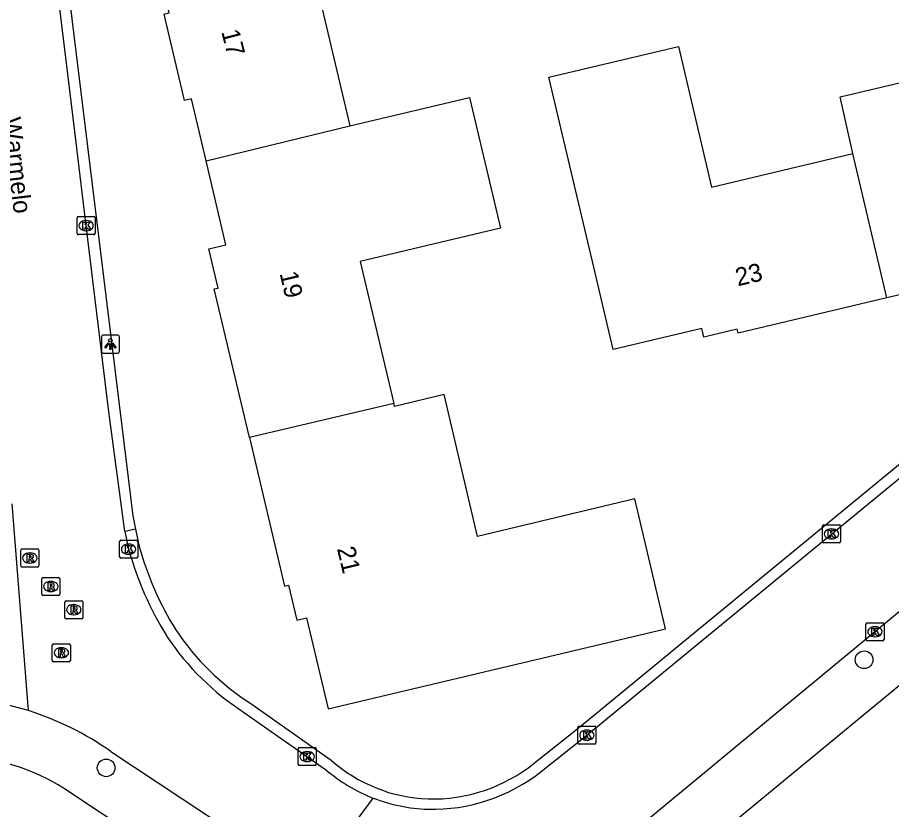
# Model space of a CAD drawing. Extents: x 157663 to 158496, y 379212 to 380934.
# Drawn here: x 158156.17 to 158204.55, y 380451.91 to 380495.74 of the extents above; entities that cross this region are included whole.
import ezdxf

# ---------------------------------------------------------------- set-up
doc = ezdxf.new("R2010")
doc.units = 0
for name, color, linetype in [('IMGEO_Boom', 7, 'Continuous'), ('IMGEO_Kolk', 7, 'Continuous'), ('IMGEO_Lichtpunt', 7, 'Continuous'), ('IMGEO_Openbare_ruimte_label', 7, 'Continuous'), ('IMGEO_Pand', 7, 'Continuous'), ('IMGEO_Pand_nummerreeks', 7, 'Continuous'), ('IMGEO_Rijbaan_lokaal_open', 7, 'Continuous'), ('IMGEO_Rioolput', 7, 'Continuous'), ('IMGEO_Voetpad_open', 7, 'Continuous')]:
    doc.layers.add(name, color=color, linetype=linetype)

msp = doc.modelspace()

# ---------------------------------------------------------------- linework, layer by layer
at = {"layer": 'IMGEO_Boom'}
for centre in [(158203.034, 380460.198), (158161.074, 380454.213)]:
    msp.add_circle(centre, 0.489, dxfattribs=at)
at = {"layer": 'IMGEO_Kolk'}
for p, q in [((158159.462, 380483.793), (158159.462, 380484.645)), ((158159.537, 380484.719), (158160.389, 380484.719)), ((158159.95, 380484.499), (158159.975, 380484.499)), ((158160.463, 380484.645), (158160.463, 380483.793)), ((158159.973, 380483.939), (158159.948, 380483.939)), ((158160.389, 380483.719), (158159.537, 380483.719)), ((158200.727, 380466.732), (158200.727, 380467.584)), ((158200.802, 380467.658), (158201.654, 380467.658)), ((158201.215, 380467.438), (158201.24, 380467.438)), ((158201.728, 380467.584), (158201.728, 380466.732)), ((158161.818, 380465.888), (158161.818, 380466.74)), ((158161.893, 380466.814), (158162.745, 380466.814)), ((158162.306, 380466.594), (158162.331, 380466.594)), ((158162.819, 380466.74), (158162.819, 380465.888)), ((158201.654, 380466.658), (158200.802, 380466.658)), ((158201.238, 380466.878), (158201.213, 380466.878)), ((158162.329, 380466.034), (158162.304, 380466.034)), ((158162.745, 380465.814), (158161.893, 380465.814)), ((158203.135, 380461.319), (158203.135, 380462.171)), ((158203.21, 380462.245), (158204.062, 380462.245)), ((158204.136, 380462.171), (158204.136, 380461.319)), ((158203.623, 380462.025), (158203.648, 380462.025)), ((158204.062, 380461.245), (158203.21, 380461.245)), ((158203.646, 380461.465), (158203.621, 380461.465)), ((158187.188, 380455.594), (158187.188, 380456.446)), ((158187.263, 380456.52), (158188.115, 380456.52)), ((158187.676, 380456.3), (158187.701, 380456.3)), ((158188.189, 380456.446), (158188.189, 380455.594)), ((158171.775, 380455.337), (158172.627, 380455.337)), ((158188.115, 380455.52), (158187.263, 380455.52)), ((158187.699, 380455.74), (158187.674, 380455.74)), ((158171.7, 380454.411), (158171.7, 380455.263)), ((158172.188, 380455.117), (158172.213, 380455.117)), ((158172.701, 380455.263), (158172.701, 380454.411)), ((158172.627, 380454.337), (158171.775, 380454.337)), ((158172.211, 380454.557), (158172.186, 380454.557))]:
    msp.add_line(p, q, dxfattribs=at)
for points in [[(158159.462, 380483.793), (158159.462, 380484.645)], [(158159.537, 380484.719), (158160.389, 380484.719)], [(158159.783, 380484.419), (158159.906, 380484.419), (158159.906, 380484.268), (158160.036, 380484.419), (158160.2, 380484.419), (158160.054, 380484.268), (158160.207, 380484.019), (158160.055, 380484.019), (158159.97, 380484.183), (158159.906, 380484.116), (158159.906, 380484.019), (158159.783, 380484.019), (158159.783, 380484.419)], [(158160.463, 380484.645), (158160.463, 380483.793)], [(158160.389, 380483.719), (158159.537, 380483.719)], [(158200.727, 380466.732), (158200.727, 380467.584)], [(158200.802, 380467.658), (158201.654, 380467.658)], [(158201.728, 380467.584), (158201.728, 380466.732)], [(158201.048, 380467.358), (158201.171, 380467.358), (158201.171, 380467.207), (158201.301, 380467.358), (158201.465, 380467.358), (158201.319, 380467.207), (158201.472, 380466.958), (158201.32, 380466.958), (158201.235, 380467.122), (158201.171, 380467.055), (158201.171, 380466.958), (158201.048, 380466.958), (158201.048, 380467.358)], [(158161.818, 380465.888), (158161.818, 380466.74)], [(158161.893, 380466.814), (158162.745, 380466.814)], [(158162.139, 380466.514), (158162.262, 380466.514), (158162.262, 380466.363), (158162.392, 380466.514), (158162.556, 380466.514), (158162.41, 380466.363), (158162.563, 380466.114), (158162.411, 380466.114), (158162.326, 380466.278), (158162.262, 380466.211), (158162.262, 380466.114), (158162.139, 380466.114), (158162.139, 380466.514)], [(158162.819, 380466.74), (158162.819, 380465.888)], [(158201.654, 380466.658), (158200.802, 380466.658)], [(158162.745, 380465.814), (158161.893, 380465.814)], [(158203.135, 380461.319), (158203.135, 380462.171)], [(158203.21, 380462.245), (158204.062, 380462.245)], [(158204.136, 380462.171), (158204.136, 380461.319)], [(158203.456, 380461.945), (158203.579, 380461.945), (158203.579, 380461.794), (158203.709, 380461.945), (158203.873, 380461.945), (158203.727, 380461.794), (158203.88, 380461.545), (158203.728, 380461.545), (158203.643, 380461.709), (158203.579, 380461.642), (158203.579, 380461.545), (158203.456, 380461.545), (158203.456, 380461.945)], [(158204.062, 380461.245), (158203.21, 380461.245)], [(158187.188, 380455.594), (158187.188, 380456.446)], [(158187.263, 380456.52), (158188.115, 380456.52)], [(158188.189, 380456.446), (158188.189, 380455.594)], [(158187.509, 380456.22), (158187.632, 380456.22), (158187.632, 380456.069), (158187.762, 380456.22), (158187.926, 380456.22), (158187.78, 380456.069), (158187.933, 380455.82), (158187.781, 380455.82), (158187.696, 380455.984), (158187.632, 380455.917), (158187.632, 380455.82), (158187.509, 380455.82), (158187.509, 380456.22)], [(158171.775, 380455.337), (158172.627, 380455.337)], [(158188.115, 380455.52), (158187.263, 380455.52)], [(158171.7, 380454.411), (158171.7, 380455.263)], [(158172.021, 380455.037), (158172.144, 380455.037), (158172.144, 380454.886), (158172.274, 380455.037), (158172.438, 380455.037), (158172.292, 380454.886), (158172.445, 380454.637), (158172.293, 380454.637), (158172.208, 380454.801), (158172.144, 380454.734), (158172.144, 380454.637), (158172.021, 380454.637), (158172.021, 380455.037)], [(158172.701, 380455.263), (158172.701, 380454.411)], [(158172.627, 380454.337), (158171.775, 380454.337)]]:
    msp.add_lwpolyline(points, dxfattribs=at)
for centre, start, end in [((158159.539, 380484.643), 91.552, 178.448), ((158159.539, 380484.643), 91.552, 178.448), ((158160.387, 380484.643), 1.552, 88.448), ((158160.387, 380484.643), 1.552, 88.448), ((158159.539, 380483.795), 181.552, 268.448), ((158159.539, 380483.795), 181.552, 268.448), ((158160.387, 380483.795), 271.552, 358.448), ((158160.387, 380483.795), 271.552, 358.448), ((158200.804, 380467.582), 91.552, 178.448), ((158200.804, 380467.582), 91.552, 178.448), ((158201.652, 380467.582), 1.552, 88.448), ((158201.652, 380467.582), 1.552, 88.448), ((158161.895, 380466.738), 91.552, 178.448), ((158161.895, 380466.738), 91.552, 178.448), ((158162.743, 380466.738), 1.552, 88.448), ((158162.743, 380466.738), 1.552, 88.448), ((158200.804, 380466.734), 181.552, 268.448), ((158200.804, 380466.734), 181.552, 268.448), ((158201.652, 380466.734), 271.552, 358.448), ((158201.652, 380466.734), 271.552, 358.448), ((158161.895, 380465.89), 181.552, 268.448), ((158161.895, 380465.89), 181.552, 268.448), ((158162.743, 380465.89), 271.552, 358.448), ((158162.743, 380465.89), 271.552, 358.448), ((158203.212, 380462.169), 91.552, 178.448), ((158203.212, 380462.169), 91.552, 178.448), ((158204.06, 380462.169), 1.552, 88.448), ((158204.06, 380462.169), 1.552, 88.448), ((158203.212, 380461.321), 181.552, 268.448), ((158203.212, 380461.321), 181.552, 268.448), ((158204.06, 380461.321), 271.552, 358.448), ((158204.06, 380461.321), 271.552, 358.448), ((158187.265, 380456.444), 91.552, 178.448), ((158187.265, 380456.444), 91.552, 178.448), ((158188.113, 380456.444), 1.552, 88.448), ((158188.113, 380456.444), 1.552, 88.448), ((158171.777, 380455.261), 91.552, 178.448), ((158171.777, 380455.261), 91.552, 178.448), ((158172.625, 380455.261), 1.552, 88.448), ((158172.625, 380455.261), 1.552, 88.448), ((158187.265, 380455.596), 181.552, 268.448), ((158187.265, 380455.596), 181.552, 268.448), ((158188.113, 380455.596), 271.552, 358.448), ((158188.113, 380455.596), 271.552, 358.448), ((158171.777, 380454.413), 181.552, 268.448), ((158171.777, 380454.413), 181.552, 268.448), ((158172.625, 380454.413), 271.552, 358.448), ((158172.625, 380454.413), 271.552, 358.448)]:
    msp.add_arc(centre, 0.0765, start, end, dxfattribs=at)
for centre, major_axis, ratio, start_param, end_param in [((158159.949, 380484.219), (-0.387, 0.002), 0.722429, 4.712389, 7.853982), ((158159.974, 380484.219), (-0.39, 0.002), 0.717154, 1.570796, 4.712389), ((158201.214, 380467.158), (-0.387, 0.002), 0.722429, 4.712389, 7.853982), ((158201.239, 380467.158), (-0.39, 0.002), 0.717154, 1.570796, 4.712389), ((158162.305, 380466.314), (-0.387, 0.002), 0.722429, 4.712389, 7.853982), ((158162.33, 380466.314), (-0.39, 0.002), 0.717154, 1.570796, 4.712389), ((158203.622, 380461.745), (-0.387, 0.002), 0.722429, 4.712389, 7.853982), ((158203.647, 380461.745), (-0.39, 0.002), 0.717154, 1.570796, 4.712389), ((158187.675, 380456.02), (-0.387, 0.002), 0.722429, 4.712389, 7.853982), ((158187.7, 380456.02), (-0.39, 0.002), 0.717154, 1.570796, 4.712389), ((158172.187, 380454.837), (-0.387, 0.002), 0.722429, 4.712389, 7.853982), ((158172.212, 380454.837), (-0.39, 0.002), 0.717154, 1.570796, 4.712389)]:
    msp.add_ellipse(centre, major_axis=major_axis, ratio=ratio, start_param=start_param, end_param=end_param, dxfattribs=at)
at = {"layer": 'IMGEO_Lichtpunt'}
for p, q in [((158160.81, 380478.07), (158160.81, 380477.263)), ((158160.81, 380478.07), (158160.81, 380477.263)), ((158161.712, 380478.165), (158160.904, 380478.165)), ((158161.712, 380478.165), (158160.904, 380478.165)), ((158161.806, 380477.263), (158161.806, 380478.07)), ((158161.806, 380477.263), (158161.806, 380478.07)), ((158160.904, 380477.169), (158161.712, 380477.169)), ((158160.904, 380477.169), (158161.712, 380477.169))]:
    msp.add_line(p, q, dxfattribs=at)
for points in [[(158161.184, 380477.734), (158161.223, 380477.706), (158161.035, 380477.444), (158160.997, 380477.471), (158161.184, 380477.734)], [(158161.286, 380477.686), (158161.333, 380477.686), (158161.333, 380477.364), (158161.286, 380477.364), (158161.286, 380477.686)], [(158161.396, 380477.706), (158161.434, 380477.733), (158161.621, 380477.471), (158161.582, 380477.443), (158161.396, 380477.706)]]:
    msp.add_lwpolyline(points, dxfattribs=at)
msp.add_circle((158161.309, 380477.868), 0.0994, dxfattribs=at)
for centre, start, end in [((158160.904, 380478.07), 90, 180), ((158160.904, 380478.07), 90, 180), ((158161.712, 380478.07), 0, 90), ((158161.712, 380478.07), 0, 90), ((158160.904, 380477.263), 180, 270), ((158160.904, 380477.263), 180, 270), ((158161.712, 380477.263), 270, 0), ((158161.712, 380477.263), 270, 360)]:
    msp.add_arc(centre, 0.0946, start, end, dxfattribs=at)
at = {"layer": 'IMGEO_Pand'}
for points in [[(158166.611, 380487.799), (158165.8, 380491.229), (158165.409, 380491.136), (158164.278, 380495.921), (158164.571, 380495.991), (158164.065, 380498.13), (158164.937, 380498.336), (158164.546, 380500), (158163.742, 380503.42)], [(158202.404, 380488.204), (158201.707, 380491.345), (158209.759, 380493.249), (158208.154, 380500), (158207.911, 380501.03), (158215.154, 380502.738)], [(158179.696, 380500.899), (158179.908, 380500), (158180.1, 380499.38), (158172.701, 380497.63), (158174.566, 380489.746)], [(158216.91, 380495.301), (158218.736, 380487.571), (158213.719, 380486.384), (158213.864, 380485.77), (158211.883, 380485.301), (158212.009, 380485.167), (158207.204, 380484.03), (158207.903, 380481.075), (158204.29, 380480.221)], [(158204.29, 380480.221), (158196.055, 380478.273), (158196.004, 380478.487), (158194.161, 380478.051), (158194.048, 380478.53), (158189.142, 380477.37), (158187.991, 380482.236), (158185.578, 380492.438), (158192.751, 380494.135), (158194.591, 380486.356), (158202.404, 380488.204)], [(158174.566, 380489.746), (158181.189, 380491.313), (158182.901, 380484.076), (158175.139, 380482.241), (158176.998, 380474.379)], [(158166.611, 380487.799), (158174.566, 380489.746)], [(158204.29, 380480.221), (158202.404, 380488.204)], [(158169.001, 380472.489), (158167.056, 380480.713), (158167.279, 380480.765), (158166.765, 380482.938), (158167.708, 380483.161), (158166.611, 380487.799)], [(158169.001, 380472.489), (158170.947, 380464.26), (158171.175, 380464.314), (158171.632, 380462.381), (158172.167, 380462.507), (158173.356, 380457.478), (158192.041, 380461.897), (158190.891, 380466.763), (158190.336, 380469.109), (158181.634, 380467.014), (158179.778, 380474.865), (158177.036, 380474.216), (158176.998, 380474.379)], [(158176.998, 380474.379), (158169.001, 380472.489)]]:
    msp.add_lwpolyline(points, dxfattribs=at)
at = {"layer": 'IMGEO_Rijbaan_lokaal_open'}
for points in [[(158162.104, 380467.3), (158161.202, 380474.058), (158159.819, 380485.438), (158159.338, 380489.435), (158157.889, 380501.383), (158157.419, 380505.143), (158156.56, 380512.003)], [(158185.161, 380454.009), (158187.689, 380456.02), (158203.743, 380469.21), (158209.588, 380474.011), (158227.179, 380488.487)], [(158233.356, 380486.647), (158230.451, 380483.891), (158221.604, 380476.545), (158218.116, 380473.682), (158209.246, 380466.364), (158206.145, 380463.806), (158197.636, 380456.782), (158194.731, 380454.379), (158190.688, 380451.037), (158189.757, 380450.307)], [(158156.78, 380457.379), (158155.878, 380468.826)], [(158162.104, 380467.3), (158162.319, 380466.314)], [(158168.731, 380457.266), (158173.218, 380454.125)], [(158161.334, 380455.114), (158169.246, 380449.877)], [(158172.506, 380447.982), (158175.859, 380452.543)]]:
    msp.add_lwpolyline(points, dxfattribs=at)
for centre, radius, start, end in [((158179.845, 380471.137), 18.177, 195.3867, 212.0502), ((158176.676, 380469.632), 14.699, 213.634, 237.2808), ((158152.632, 380444.177), 13.838, 72.5578, 96.6565), ((158151.749, 380441.553), 16.606, 54.7469, 72.3649), ((158179.21, 380461.133), 9.22, 229.4675, 248.688), ((158179.118, 380461.704), 9.784, 268.5759, 308.1408), ((158179.195, 380461.124), 9.207, 248.7572, 268.0098)]:
    msp.add_arc(centre, radius, start, end, dxfattribs=at)
at = {"layer": 'IMGEO_Rioolput'}
for p, q in [((158156.35, 380465.4), (158156.35, 380466.252)), ((158156.425, 380466.326), (158157.277, 380466.326)), ((158156.838, 380466.106), (158156.863, 380466.106)), ((158157.351, 380466.252), (158157.351, 380465.4)), ((158156.861, 380465.546), (158156.836, 380465.546)), ((158157.277, 380465.326), (158156.425, 380465.326)), ((158157.51, 380463.823), (158157.51, 380464.675)), ((158157.585, 380464.749), (158158.437, 380464.749)), ((158157.998, 380464.529), (158158.023, 380464.529)), ((158158.511, 380464.675), (158158.511, 380463.823)), ((158158.437, 380463.749), (158157.585, 380463.749)), ((158158.021, 380463.969), (158157.996, 380463.969)), ((158158.778, 380462.538), (158158.778, 380463.39)), ((158158.853, 380463.464), (158159.705, 380463.464)), ((158159.266, 380463.244), (158159.291, 380463.244)), ((158159.779, 380463.39), (158159.779, 380462.538)), ((158159.289, 380462.684), (158159.264, 380462.684)), ((158159.705, 380462.464), (158158.853, 380462.464)), ((158158.093, 380460.156), (158158.093, 380461.008)), ((158158.168, 380461.082), (158159.02, 380461.082)), ((158158.581, 380460.862), (158158.606, 380460.862)), ((158159.094, 380461.008), (158159.094, 380460.156)), ((158158.604, 380460.302), (158158.579, 380460.302)), ((158159.02, 380460.082), (158158.168, 380460.082))]:
    msp.add_line(p, q, dxfattribs=at)
for points in [[(158156.35, 380465.4), (158156.35, 380466.252)], [(158156.425, 380466.326), (158157.277, 380466.326)], [(158156.939, 380466.024), (158156.687, 380466.026), (158156.687, 380465.626)], [(158156.865, 380465.945), (158156.811, 380465.945), (158156.811, 380465.864)], [(158157.351, 380466.252), (158157.351, 380465.4)], [(158156.687, 380465.626), (158156.811, 380465.626), (158156.811, 380465.788), (158156.822, 380465.788)], [(158156.811, 380465.864), (158156.863, 380465.864)], [(158156.869, 380465.759), (158156.94, 380465.626), (158157.08, 380465.626), (158157.015, 380465.752)], [(158157.277, 380465.326), (158156.425, 380465.326)], [(158157.51, 380463.823), (158157.51, 380464.675)], [(158157.585, 380464.749), (158158.437, 380464.749)], [(158158.511, 380464.675), (158158.511, 380463.823)], [(158158.099, 380464.447), (158157.847, 380464.449), (158157.847, 380464.049)], [(158157.847, 380464.049), (158157.971, 380464.049), (158157.971, 380464.211), (158157.982, 380464.211)], [(158158.025, 380464.368), (158157.971, 380464.368), (158157.971, 380464.287)], [(158157.971, 380464.287), (158158.023, 380464.287)], [(158158.029, 380464.182), (158158.1, 380464.049), (158158.24, 380464.049), (158158.175, 380464.175)], [(158158.437, 380463.749), (158157.585, 380463.749)], [(158158.778, 380462.538), (158158.778, 380463.39)], [(158158.853, 380463.464), (158159.705, 380463.464)], [(158159.367, 380463.162), (158159.115, 380463.164), (158159.115, 380462.764)], [(158159.293, 380463.083), (158159.239, 380463.083), (158159.239, 380463.002)], [(158159.779, 380463.39), (158159.779, 380462.538)], [(158159.115, 380462.764), (158159.239, 380462.764), (158159.239, 380462.926), (158159.25, 380462.926)], [(158159.239, 380463.002), (158159.291, 380463.002)], [(158159.297, 380462.897), (158159.368, 380462.764), (158159.508, 380462.764), (158159.443, 380462.89)], [(158159.705, 380462.464), (158158.853, 380462.464)], [(158158.093, 380460.156), (158158.093, 380461.008)], [(158158.168, 380461.082), (158159.02, 380461.082)], [(158158.682, 380460.78), (158158.43, 380460.782), (158158.43, 380460.382)], [(158158.608, 380460.701), (158158.554, 380460.701), (158158.554, 380460.62)], [(158159.094, 380461.008), (158159.094, 380460.156)], [(158158.43, 380460.382), (158158.554, 380460.382), (158158.554, 380460.544), (158158.565, 380460.544)], [(158158.554, 380460.62), (158158.606, 380460.62)], [(158158.612, 380460.515), (158158.683, 380460.382), (158158.823, 380460.382), (158158.758, 380460.508)], [(158159.02, 380460.082), (158158.168, 380460.082)]]:
    msp.add_lwpolyline(points, dxfattribs=at)
for centre, radius, start, end in [((158156.427, 380466.25), 0.0765, 91.552, 178.448), ((158156.427, 380466.25), 0.0765, 91.552, 178.448), ((158156.871, 380465.849), 0.0964, 77.0061, 93.1865), ((158156.938, 380465.914), 0.109, 350.3612, 89.416), ((158157.275, 380466.25), 0.0765, 1.552, 88.448), ((158157.275, 380466.25), 0.0765, 1.552, 88.448), ((158156.821, 380465.735), 0.0533, 26.0293, 88.6989), ((158156.847, 380466.053), 0.19, 274.7715, 282.9687), ((158156.885, 380465.906), 0.0378, 276.6634, 79.6772), ((158156.936, 380465.914), 0.112, 277.5842, 350.9817), ((158156.92, 380465.699), 0.108, 29.5134, 73.7905), ((158156.427, 380465.402), 0.0765, 181.552, 268.448), ((158156.427, 380465.402), 0.0765, 181.552, 268.448), ((158157.275, 380465.402), 0.0765, 271.552, 358.448), ((158157.275, 380465.402), 0.0765, 271.552, 358.448), ((158157.587, 380464.673), 0.0765, 91.552, 178.448), ((158157.587, 380464.673), 0.0765, 91.552, 178.448), ((158158.435, 380464.673), 0.0765, 1.552, 88.448), ((158158.435, 380464.673), 0.0765, 1.552, 88.448), ((158157.981, 380464.158), 0.0533, 26.0293, 88.6989), ((158158.007, 380464.476), 0.19, 274.7715, 282.9687), ((158158.031, 380464.272), 0.0964, 77.0061, 93.1865), ((158158.045, 380464.329), 0.0378, 276.6634, 79.6772), ((158158.098, 380464.337), 0.109, 350.3612, 89.416), ((158158.096, 380464.337), 0.112, 277.5842, 350.9817), ((158158.08, 380464.122), 0.108, 29.5134, 73.7905), ((158157.587, 380463.825), 0.0765, 181.552, 268.448), ((158157.587, 380463.825), 0.0765, 181.552, 268.448), ((158158.435, 380463.825), 0.0765, 271.552, 358.448), ((158158.435, 380463.825), 0.0765, 271.552, 358.448), ((158158.855, 380463.388), 0.0765, 91.552, 178.448), ((158158.855, 380463.388), 0.0765, 91.552, 178.448), ((158159.299, 380462.987), 0.0964, 77.0061, 93.1865), ((158159.313, 380463.044), 0.0378, 276.6634, 79.6772), ((158159.366, 380463.052), 0.109, 350.3612, 89.416), ((158159.703, 380463.388), 0.0765, 1.552, 88.448), ((158159.703, 380463.388), 0.0765, 1.552, 88.448), ((158159.249, 380462.873), 0.0533, 26.0293, 88.6989), ((158159.275, 380463.191), 0.19, 274.7715, 282.9687), ((158159.364, 380463.052), 0.112, 277.5842, 350.9817), ((158159.348, 380462.837), 0.108, 29.5134, 73.7905), ((158158.855, 380462.54), 0.0765, 181.552, 268.448), ((158158.855, 380462.54), 0.0765, 181.552, 268.448), ((158159.703, 380462.54), 0.0765, 271.552, 358.448), ((158159.703, 380462.54), 0.0765, 271.552, 358.448), ((158158.17, 380461.006), 0.0765, 91.552, 178.448), ((158158.17, 380461.006), 0.0765, 91.552, 178.448), ((158158.59, 380460.809), 0.19, 274.7715, 282.9687), ((158158.614, 380460.605), 0.0964, 77.0061, 93.1865), ((158158.628, 380460.662), 0.0378, 276.6634, 79.6772), ((158158.681, 380460.67), 0.109, 350.3612, 89.416), ((158158.679, 380460.67), 0.112, 277.5842, 350.9817), ((158159.018, 380461.006), 0.0765, 1.552, 88.448), ((158159.018, 380461.006), 0.0765, 1.552, 88.448), ((158158.17, 380460.158), 0.0765, 181.552, 268.448), ((158158.17, 380460.158), 0.0765, 181.552, 268.448), ((158158.564, 380460.491), 0.0533, 26.0293, 88.6989), ((158158.663, 380460.455), 0.108, 29.5134, 73.7905), ((158159.018, 380460.158), 0.0765, 271.552, 358.448), ((158159.018, 380460.158), 0.0765, 271.552, 358.448)]:
    msp.add_arc(centre, radius, start, end, dxfattribs=at)
for centre, major_axis, ratio, start_param, end_param in [((158156.837, 380465.826), (-0.387, 0.002), 0.722429, 4.712389, 7.853982), ((158156.862, 380465.826), (-0.39, 0.002), 0.717154, 1.570796, 4.712389), ((158157.997, 380464.249), (-0.387, 0.002), 0.722429, 4.712389, 7.853982), ((158158.022, 380464.249), (-0.39, 0.002), 0.717154, 1.570796, 4.712389), ((158159.265, 380462.964), (-0.387, 0.002), 0.722429, 4.712389, 7.853982), ((158159.29, 380462.964), (-0.39, 0.002), 0.717154, 1.570796, 4.712389), ((158158.58, 380460.582), (-0.387, 0.002), 0.722429, 4.712389, 7.853982), ((158158.605, 380460.582), (-0.39, 0.002), 0.717154, 1.570796, 4.712389)]:
    msp.add_ellipse(centre, major_axis=major_axis, ratio=ratio, start_param=start_param, end_param=end_param, dxfattribs=at)
at = {"layer": 'IMGEO_Voetpad_open'}
for points in [[(158157.161, 380512.065), (158162.55, 380468.158), (158162.704, 380467.421)], [(158184.789, 380454.483), (158187.303, 380456.485), (158226.813, 380488.959)], [(158195.106, 380450.632), (158232.056, 380481.111)], [(158162.704, 380467.421), (158162.104, 380467.3)], [(158162.704, 380467.421), (158162.905, 380466.463)], [(158169.078, 380457.768), (158173.531, 380454.645)], [(158173.354, 380444.085), (158171.106, 380445.029), (158168.008, 380446.921), (158159.325, 380452.675)]]:
    msp.add_lwpolyline(points, dxfattribs=at)
for centre, radius, start, end in [((158179.991, 380471.206), 17.732, 195.5141, 211.8449), ((158176.711, 380469.678), 14.146, 213.6001, 237.3465), ((158152.546, 380443.313), 11.559, 54.0926, 98.6872), ((158179.198, 380461.005), 8.518, 228.2951, 267.9067), ((158179.131, 380461.512), 9.023, 268.4504, 308.8326)]:
    msp.add_arc(centre, radius, start, end, dxfattribs=at)

# ---------------------------------------------------------------- texts
at = {"layer": 'IMGEO_Openbare_ruimte_label'}
msp.add_text('Warmelo', height=1, rotation=276.7199, dxfattribs=at).set_placement((158155.346, 380490.159))
at = {"layer": 'IMGEO_Pand_nummerreeks'}
for s, rotation, p in [('17', 284.4727, (158167.441, 380494.952)), ('23', 13.3057, (158196.036, 380480.858)), ('19', 283.3068, (158170.672, 380481.578)), ('21', 283.3039, (158173.849, 380466.348))]:
    msp.add_text(s, height=1, rotation=rotation, dxfattribs=at).set_placement(p)

doc.saveas('drawing.dxf')
